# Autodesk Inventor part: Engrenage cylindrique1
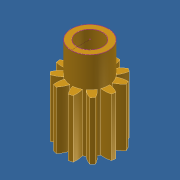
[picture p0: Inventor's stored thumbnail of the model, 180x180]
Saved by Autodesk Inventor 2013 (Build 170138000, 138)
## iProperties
Created: 2011-10
Part Number: Engrenage cylindrique1
Material: Laiton (jaune doux)
Document SubType Name: Modeling
Designer: Laur
Mass: 0.174951 g
Surface Area: 1.0732 cm^2
Volume: 0.0206553 cm^3
Density: 8.47 g/cm^3
CustomPartVersion: 1
Author: Laur
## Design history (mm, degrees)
sketch "Sketch1"
  geometry: C1 r 1.663 at (0, 0)
  constraints: 1 centre point
  dimensions: "d0" = 3.325 diameter of C1 (= da_da)
extrude "Extrusion1" new body sketch "Sketch1" distance "d1" = 3.4 (= da_b); taper "d2" = 0 deg
workplane "Work Plane2"
extrude_surface "ExtrusionSrf1" dims "d4" = 10, "d5" = 0
workplane "Work Plane8"
workplane "Work Plane9"
feature "Engrenage cylindrique" dims "da_b" = 3.4, "da_d" = 2.75, "da_aw" = 6, "da_da" = 3.325, "da_df" = 2.2, "da_dw" = 2.75, angle "da_beta" = 0 deg, "da_lefttooth" = 0, "da_righttooth" = 0
sketch "Esquisse3"
  geometry: C1 r 0.75 at (0, 0) reference
extrude "Extrusion2" cut sketch "Esquisse3" stored distance "d49" = 10; taper "d50" = 0 deg
sketch "Esquisse4"
  geometry: C1 r 0.75 at (0, 0) reference; C2 r 1.1 at (0, 0); A1 r 1.663 centre (0, 0) between (-0.797, 1.459) and (-0.996, 1.331) reference
  constraints: 1 centre point, 1 coincident
  dimensions: "d51" = 2.2 diameter of C2
extrude "Extrusion3" join sketch "Esquisse4" distance "d52" = 1.8; taper "d53" = 0 deg
sketch "Esquisse5"
  geometry: L1 (0, 0)-(0, -1.1); C1 r 0.75 at (0, 0) reference
  constraints: 2 end point, 1 vertical, 1 vertical alignment, 1 other
node "Solide1"
node "Corps solides"
node "Corps surfaciques"
sketch "Sketch2"
  geometry: C1 r 1.663 at (0, 0) reference; C2 r 1.375 at (0, 0)
  constraints: 1 centre point, 1 coincident
  dimensions: "d3" = 2.75 diameter of C2 (= da_dw)
body "Srf1"
node "Référence1"
other parameters: "d16" = 6 (= da_aw), "d17" = 0, "d34" = 2.85599 (computed from da_z), "d39" = 0, "d41" = 0, "d43" = 6 (= da_aw), "d46" = 6 (= da_aw), "d47" = 0, "d48" = 0
